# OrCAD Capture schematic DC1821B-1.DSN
size Custom; title: WITH PROGRAMMABLE OUTPUT CURRENT; rev: 1; note: DEMO CIRCUIT 1821B
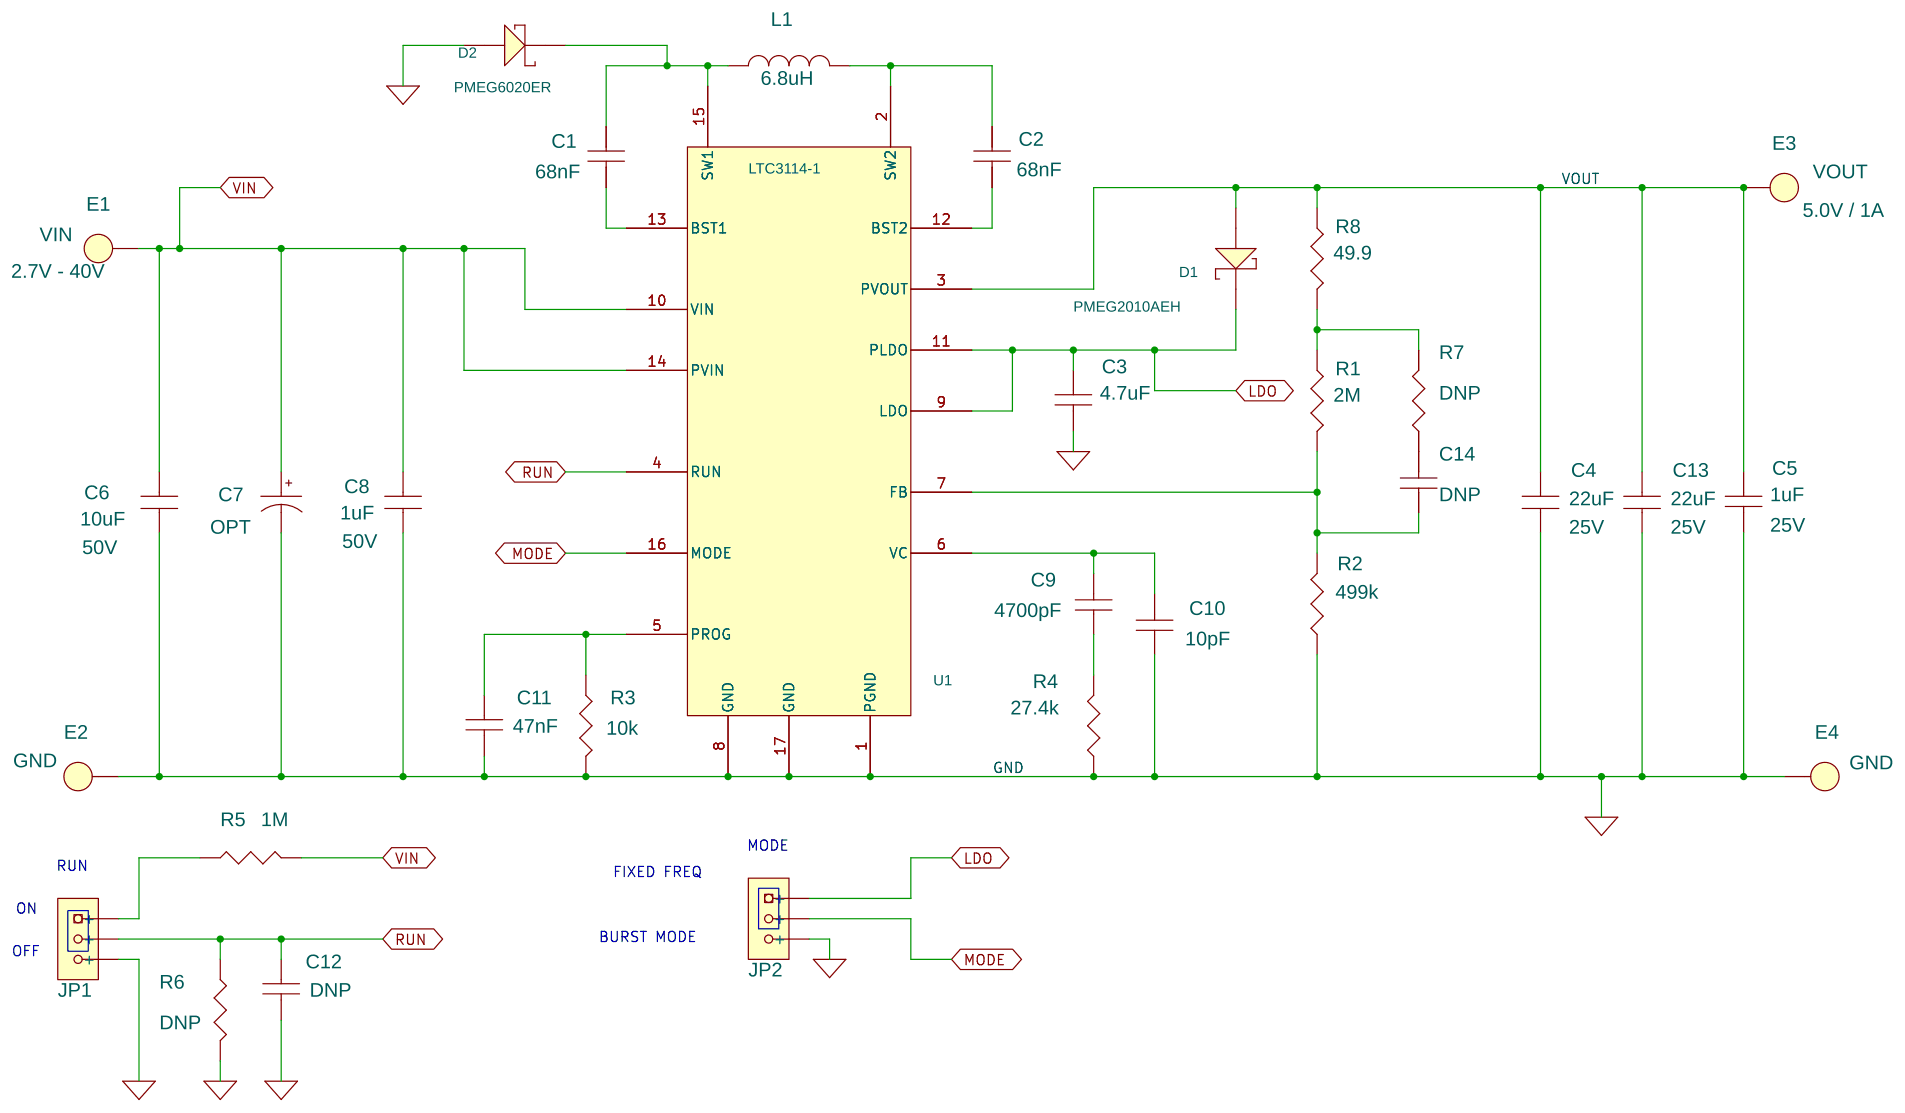
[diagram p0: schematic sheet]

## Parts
C1  68nF  [0402-SMALL]
C2  68nF  [0402-SMALL]
C3  4.7uF  [0603]
C4  22uF  [1812-1210]
C5  1uF  [0603]
C6  10uF  [2220]
C7  OPT  [CAP-63HVH33M]
C8  1uF  [1206]
C9  4700pF  [0402-SMALL]
C10  10pF  [0402-SMALL]
C11  47nF  [0402-SMALL]
C12  DNP  [0402-SMALL]
C13  22uF  [1812-1210]
C14  DNP  [0402-SMALL]
D1  PMEG2010AEH  [SOD-123]
D2  PMEG6020ER  [SOD-123]
E1  0.09"  [MILL-MAX-2501-2]
E2  0.09"  [MILL-MAX-2501-2]
E3  0.09"  [MILL-MAX-2501-2]
E4  0.09"  [MILL-MAX-2501-2]
JP1  ADR0  [2MMJUMP3]
JP2  ADR0  [2MMJUMP3]
L1  6.8uH  [IND-COILCRAFTMSS1048-472]
R1  2M  [0402-SMALL]
R2  499k  [0402-SMALL]
R3  10k  [0402-SMALL]
R4  27.4k  [0402-SMALL]
R5  1M  [0402-SMALL]
R6  DNP  [0402-SMALL]
R7  DNP  [0402-SMALL]
R8  49.9  [0402-SMALL]
U1  LTC3114-1  [DHC16DFN5X3]

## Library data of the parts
C1 C2 C11 C12 = 04025A101JAT2A
C3 = JMK107BJ105KA-T
C4 = Capacitor_1812: Voltage Rating: 25V
C5 = JMK107BJ105KA-T: 1st Part Field: 25V
C6 = Capacitor_2220: Voltage: 50V
C7 = Cap_Al_El_0
C8 = Capacitor_1206: Voltage: 50V
C9 C14 = 04023A221KAT2A
C10 = 04023A100KAT2A: 6th Part Field: (Opt.)
C13 = Capacitor_1812_1: Voltage Rating: 25V
D1 = SCHOTTKY_PMEG2010AEH
D2 = SCHOTTKY_SOD123
E1 = E_2: COMPFIXED: VIN; COMPGROUP: 2.7V - 40V
E2 E4 = E_2: COMPFIXED: GND
E3 = E_2: 1A peak: 1A peak; COMPFIXED: VOUT; COMPGROUP: 5.0V / 1A
JP1 JP2 = CON6AP_6
L1 = Inductor_MSS1048
R1 R8 = CR05-3483FM
R2 = CR05-2003FM
R3 = CR05-222JM
R4 R7 = CR05-153JM
R5 R6 = CR05-105JM
U1 = LTC3114

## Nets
GND: C3.2 C4.2 C5.2 C6.2 C7.2(-) C8.2 C10.1 C11.2 C12.2 C13.2 D2.2(A) E2.1(A) E4.1(A) JP1.3(+) JP2.3(+) R2.1 R3.2 R4.1 R6.2 U1.1(PGND) U1.8(GND) U1.17(GND)
VIN: C6.1 C7.1(+) C8.1 E1.1(A) R5.2 U1.10(VIN) U1.14(PVIN)
LDO: C3.1 D1.1(C) JP2.1(+) U1.9(LDO) U1.11(PLDO)
MODE: JP2.2(+) U1.16(MODE)
RUN: C12.1 JP1.2(+) R6.1 U1.4(RUN)
VOUT: C4.1 C5.1 C13.1 D1.2(A) E3.1(A) R8.1 U1.3(PVOUT)
N16624396: JP1.1(+) R5.1
N16633308: C14.1 R1.2 R2.2 U1.7(FB)
N16633558: R1.1 R7.2 R8.2
N16636794: C9.2 C10.2 U1.6(VC)
N16636802: C11.1 R3.1 U1.5(PROG)
N16636806: C2.1 L1.2 U1.2(SW2)
N16636810: C1.1 D2.1(C) L1.1 U1.15(SW1)
N16671819: C14.2 R7.1
N16877791: C2.2 U1.12(BST2)
N16880158: C1.2 U1.13(BST1)
N16891049: C9.1 R4.2

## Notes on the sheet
- MODE
- RUN
- FIXED FREQ
- ON
- OFF
- BURST MODE
